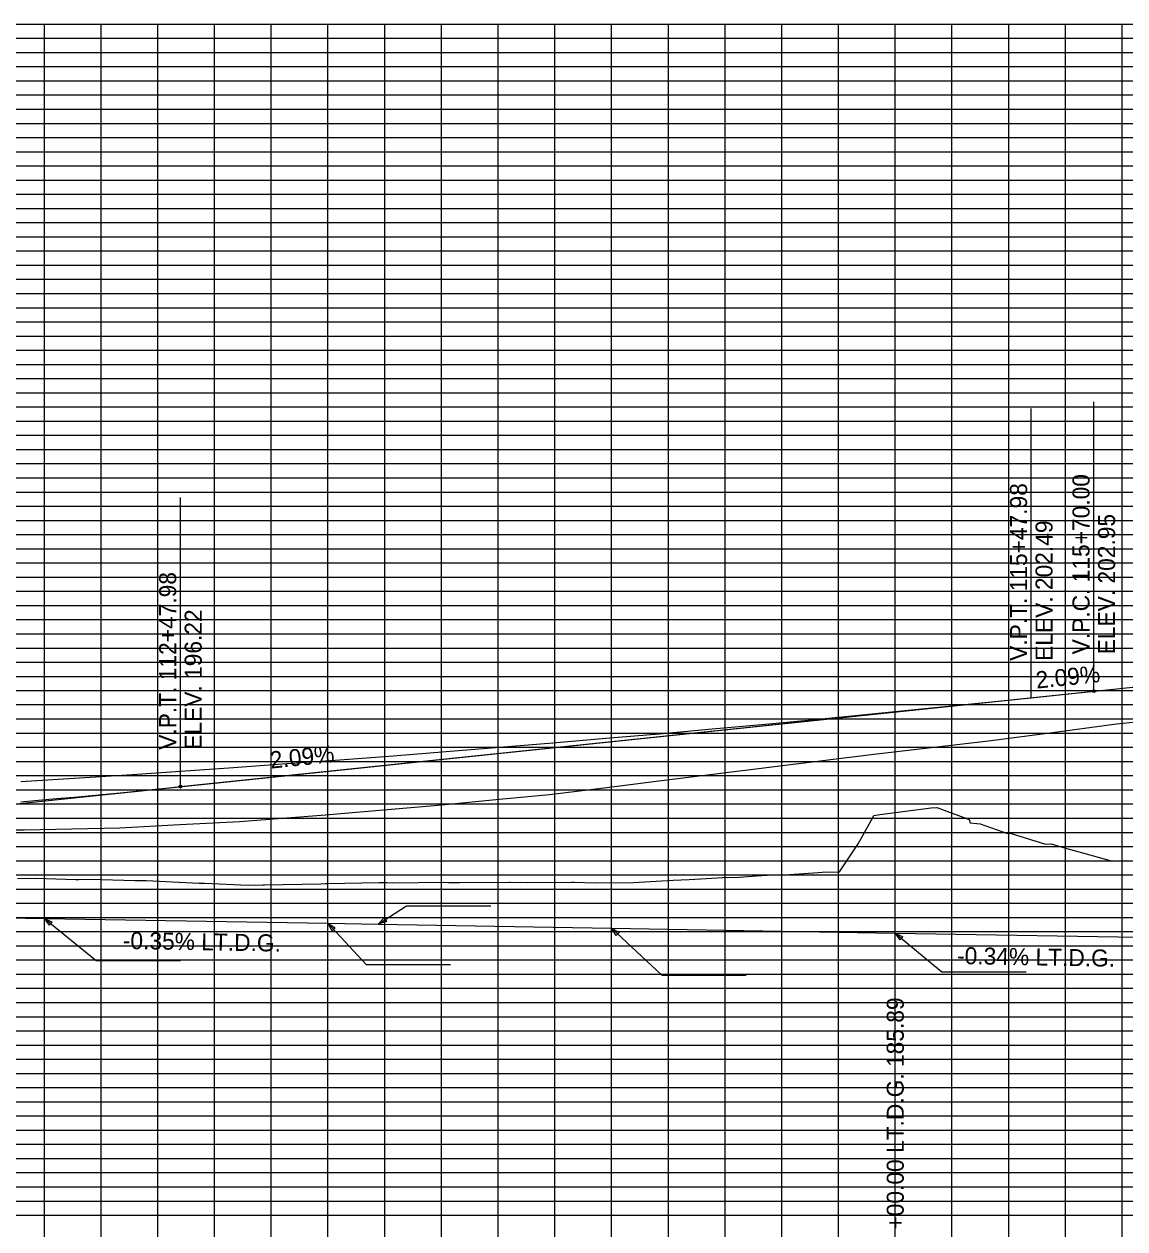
# Model space of a CAD drawing. Extents: x 1451449 to 1456010, y 297581 to 299758.
# Drawn here: x 1452672.5 to 1453060.6, y 299128.7 to 299553.5 of the extents above; entities that cross this region are included whole.
import ezdxf

# ---------------------------------------------------------------- set-up
doc = ezdxf.new("R2010")
doc.units = 0
for name, color, linetype in [('Existing Profile Grade', 7, 'Continuous'), ('Grid_Major', 7, 'Continuous'), ('Grid_Minor', 7, 'Continuous'), ('PR_Exist Surface', 7, 'Continuous'), ('PR_exist_ground', 7, 'Continuous'), ('PRF_Scratch', 7, 'Continuous'), ('Profile Annotation', 7, 'Continuous'), ('Profile Annotation Line', 7, 'Continuous'), ('Special_Ditch_LT', 7, 'Continuous')]:
    doc.layers.add(name, color=color, linetype=linetype)

msp = doc.modelspace()

# ---------------------------------------------------------------- linework, layer by layer
at = {"layer": 'Existing Profile Grade'}
msp.add_lwpolyline([(1452654.57, 299269.46), (1452672.54, 299269.39), (1452689.38, 299269.76), (1452706.22, 299270.14), (1452727.4, 299271.26), (1452748.58, 299272.38), (1452763.67, 299273.56), (1452778.75, 299274.75), (1452799.29, 299276.5), (1452819.83, 299278.26), (1452819.79, 299278.26), (1452838.79, 299280.08), (1452857.79, 299281.9), (1452877.08, 299284.29), (1452896.36, 299286.69), (1452916.28, 299289.17), (1452936.19, 299291.64), (1452954.17, 299293.85), (1452972.15, 299296.06), (1452992.35, 299298.42), (1453012.55, 299300.79), (1453035.09, 299303.78), (1453057.64, 299306.77), (1453078.47, 299308.95)], dxfattribs=at)
at = {"layer": 'Grid_Major'}
for p, q in [((1451479.67, 299553.55), (1455979.67, 299553.55)), ((1451479.67, 299553.55), (1455979.67, 299553.55)), ((1452679.67, 298953.55), (1452679.67, 299553.55)), ((1452779.67, 298953.55), (1452779.67, 299553.55)), ((1452879.67, 298953.55), (1452879.67, 299553.55)), ((1452979.67, 298953.55), (1452979.67, 299553.55)), ((1451479.67, 299503.55), (1455979.67, 299503.55)), ((1451479.67, 299453.55), (1455979.67, 299453.55)), ((1451479.67, 299403.55), (1455979.67, 299403.55)), ((1451479.67, 299353.55), (1455979.67, 299353.55)), ((1451479.67, 299303.55), (1455979.67, 299303.55)), ((1451479.67, 299253.55), (1455979.67, 299253.55)), ((1451479.67, 299203.55), (1455979.67, 299203.55)), ((1451479.67, 299153.55), (1455979.67, 299153.55))]:
    msp.add_line(p, q, dxfattribs=at)
at = {"layer": 'Grid_Minor'}
for p, q in [((1452699.67, 298953.55), (1452699.67, 299553.55)), ((1452719.67, 298953.55), (1452719.67, 299553.55)), ((1452739.67, 298953.55), (1452739.67, 299553.55)), ((1452759.67, 298953.55), (1452759.67, 299553.55)), ((1452799.67, 298953.55), (1452799.67, 299553.55)), ((1452819.67, 298953.55), (1452819.67, 299553.55)), ((1452839.67, 298953.55), (1452839.67, 299553.55)), ((1452859.67, 298953.55), (1452859.67, 299553.55)), ((1452899.67, 298953.55), (1452899.67, 299553.55)), ((1452919.67, 298953.55), (1452919.67, 299553.55)), ((1452939.67, 298953.55), (1452939.67, 299553.55)), ((1452959.67, 298953.55), (1452959.67, 299553.55)), ((1452999.67, 298953.55), (1452999.67, 299553.55)), ((1453019.67, 298953.55), (1453019.67, 299553.55)), ((1453039.67, 298953.55), (1453039.67, 299553.55)), ((1453059.67, 298953.55), (1453059.67, 299553.55)), ((1451479.67, 299548.55), (1455979.67, 299548.55)), ((1451479.67, 299543.55), (1455979.67, 299543.55)), ((1451479.67, 299538.55), (1455979.67, 299538.55)), ((1451479.67, 299533.55), (1455979.67, 299533.55)), ((1451479.67, 299528.55), (1455979.67, 299528.55)), ((1451479.67, 299523.55), (1455979.67, 299523.55)), ((1451479.67, 299518.55), (1455979.67, 299518.55)), ((1451479.67, 299513.55), (1455979.67, 299513.55)), ((1451479.67, 299508.55), (1455979.67, 299508.55)), ((1451479.67, 299498.55), (1455979.67, 299498.55)), ((1451479.67, 299493.55), (1455979.67, 299493.55)), ((1451479.67, 299488.55), (1455979.67, 299488.55)), ((1451479.67, 299483.55), (1455979.67, 299483.55)), ((1451479.67, 299478.55), (1455979.67, 299478.55)), ((1451479.67, 299473.55), (1455979.67, 299473.55)), ((1451479.67, 299468.55), (1455979.67, 299468.55)), ((1451479.67, 299463.55), (1455979.67, 299463.55)), ((1451479.67, 299458.55), (1455979.67, 299458.55)), ((1451479.67, 299448.55), (1455979.67, 299448.55)), ((1451479.67, 299443.55), (1455979.67, 299443.55)), ((1451479.67, 299438.55), (1455979.67, 299438.55)), ((1451479.67, 299433.55), (1455979.67, 299433.55)), ((1451479.67, 299428.55), (1455979.67, 299428.55)), ((1451479.67, 299423.55), (1455979.67, 299423.55)), ((1451479.67, 299418.55), (1455979.67, 299418.55)), ((1451479.67, 299413.55), (1455979.67, 299413.55)), ((1451479.67, 299408.55), (1455979.67, 299408.55)), ((1451479.67, 299398.55), (1455979.67, 299398.55)), ((1451479.67, 299393.55), (1455979.67, 299393.55)), ((1451479.67, 299388.55), (1455979.67, 299388.55)), ((1451479.67, 299383.55), (1455979.67, 299383.55)), ((1451479.67, 299378.55), (1455979.67, 299378.55)), ((1451479.67, 299373.55), (1455979.67, 299373.55)), ((1451479.67, 299368.55), (1455979.67, 299368.55)), ((1451479.67, 299363.55), (1455979.67, 299363.55)), ((1451479.67, 299358.55), (1455979.67, 299358.55)), ((1451479.67, 299348.55), (1455979.67, 299348.55)), ((1451479.67, 299343.55), (1455979.67, 299343.55)), ((1451479.67, 299338.55), (1455979.67, 299338.55)), ((1451479.67, 299333.55), (1455979.67, 299333.55)), ((1451479.67, 299328.55), (1455979.67, 299328.55)), ((1451479.67, 299323.55), (1455979.67, 299323.55)), ((1451479.67, 299318.55), (1455979.67, 299318.55)), ((1451482.2, 299313.64), (1455982.2, 299313.64)), ((1451479.67, 299308.55), (1455979.67, 299308.55)), ((1451479.67, 299298.55), (1455979.67, 299298.55)), ((1451479.67, 299293.55), (1455979.67, 299293.55)), ((1451479.67, 299288.55), (1455979.67, 299288.55)), ((1451479.67, 299283.55), (1455979.67, 299283.55)), ((1451479.67, 299278.55), (1455979.67, 299278.55)), ((1451479.67, 299273.55), (1455979.67, 299273.55)), ((1451479.67, 299268.55), (1455979.67, 299268.55)), ((1451479.67, 299263.55), (1455979.67, 299263.55)), ((1451479.67, 299258.55), (1455979.67, 299258.55)), ((1451479.67, 299248.55), (1455979.67, 299248.55)), ((1451479.67, 299243.55), (1455979.67, 299243.55)), ((1451479.67, 299238.55), (1455979.67, 299238.55)), ((1451479.67, 299233.55), (1455979.67, 299233.55)), ((1451479.67, 299228.55), (1455979.67, 299228.55)), ((1451479.67, 299223.55), (1455979.67, 299223.55)), ((1451479.67, 299218.55), (1455979.67, 299218.55)), ((1451479.67, 299213.55), (1455979.67, 299213.55)), ((1451479.67, 299208.55), (1455979.67, 299208.55)), ((1451479.67, 299198.55), (1455979.67, 299198.55)), ((1451479.67, 299193.55), (1455979.67, 299193.55)), ((1451479.67, 299188.55), (1455979.67, 299188.55)), ((1451479.67, 299183.55), (1455979.67, 299183.55)), ((1451479.67, 299178.55), (1455979.67, 299178.55)), ((1451479.67, 299173.55), (1455979.67, 299173.55)), ((1451479.67, 299168.55), (1455979.67, 299168.55)), ((1451479.67, 299163.55), (1455979.67, 299163.55)), ((1451479.67, 299158.55), (1455979.67, 299158.55)), ((1451479.67, 299148.55), (1455979.67, 299148.55)), ((1451479.67, 299143.55), (1455979.67, 299143.55)), ((1451479.67, 299138.55), (1455979.67, 299138.55)), ((1451479.67, 299133.55), (1455979.67, 299133.55))]:
    msp.add_line(p, q, dxfattribs=at)
at = {"layer": 'PR_Exist Surface'}
msp.add_lwpolyline([(1452670.16, 299252.28), (1452676.62, 299252.38), (1452690.76, 299251.94), (1452691.87, 299251.96), (1452695.98, 299252.01), (1452711.61, 299251.53), (1452713.59, 299251.54), (1452715.57, 299251.57), (1452734.23, 299250.68), (1452735.31, 299250.64), (1452736.18, 299250.6), (1452751.52, 299249.9), (1452756.73, 299249.99), (1452757.03, 299250), (1452757.27, 299250.01), (1452777.2, 299250.42), (1452778.75, 299250.47), (1452779.54, 299250.49), (1452797.66, 299250.89), (1452800.47, 299250.83), (1452802.51, 299250.79), (1452820.56, 299250.96), (1452822.18, 299250.92), (1452826.11, 299250.82), (1452843.48, 299251), (1452843.9, 299250.98), (1452849.86, 299250.82), (1452865.62, 299250.99), (1452866.41, 299251), (1452873.85, 299250.75), (1452887.34, 299250.92), (1452889.35, 299250.95), (1452901.4, 299251.73), (1452907.02, 299251.87), (1452909.06, 299252), (1452918.86, 299252.64), (1452924.69, 299252.79), (1452930.78, 299253.19), (1452936.36, 299253.56), (1452942.37, 299253.71), (1452952.49, 299254.39), (1452953.9, 299254.49), (1452960.05, 299254.64), (1452966.63, 299264.54), (1452970.51, 299271.47), (1452972.09, 299274.54), (1452974.21, 299274.82), (1452992.38, 299277.24), (1452994.39, 299277.35), (1452995.93, 299276.77), (1453005.69, 299273.09), (1453006.14, 299271.95), (1453009.65, 299271.53), (1453017.65, 299268.74), (1453019.26, 299268.18), (1453020.21, 299268.23), (1453032.61, 299264.37), (1453034.62, 299264.45), (1453039.37, 299263.11), (1453046.21, 299261.19), (1453056.25, 299258.39), (1453060, 299258.49), (1453061.09, 299258.58)], dxfattribs=at)
at = {"layer": 'PR_exist_ground'}
for p, q in [((1453027.64, 299316.01), (1453049.67, 299318.31)), ((1453027.64, 299316.01), (1453049.67, 299318.31)), ((1453027.64, 299316.01), (1453049.67, 299318.31)), ((1453027.64, 299316.01), (1453049.67, 299318.31)), ((1453027.64, 299316.01), (1453049.67, 299318.31)), ((1452810.4, 299242.6), (1452837.14, 299242.6)), ((1452700.88, 299223.34), (1452727.63, 299223.34)), ((1452796.1, 299221.97), (1452822.85, 299221.97)), ((1452900.4, 299218.21), (1452927.15, 299218.21)), ((1452999.07, 299219.31), (1453025.82, 299219.31))]:
    msp.add_line(p, q, dxfattribs=at)
for points in [[(1453049.67, 299318.31), (1453063.42, 299319.72)], [(1453049.67, 299318.31), (1453063.42, 299319.72)], [(1453049.67, 299318.31), (1453063.42, 299319.72)], [(1453049.67, 299318.31), (1453063.42, 299319.72)], [(1453049.67, 299318.31), (1453063.42, 299319.72)], [(1452671.39, 299286.5), (1452690.14, 299287.67), (1452708.89, 299288.88), (1452727.64, 299290.13), (1452746.39, 299291.43), (1452765.14, 299292.77), (1452783.89, 299294.15), (1452802.64, 299295.58), (1452821.39, 299297.04), (1452840.14, 299298.55), (1452858.89, 299300.11), (1452877.64, 299301.7), (1452896.39, 299303.34), (1452915.14, 299305.02), (1452933.89, 299306.75), (1452952.64, 299308.51), (1452971.39, 299310.32), (1452990.14, 299312.18), (1453008.89, 299314.07), (1453027.64, 299316.01)], [(1452671.39, 299286.5), (1452690.14, 299287.67), (1452708.89, 299288.88), (1452727.64, 299290.13), (1452746.39, 299291.43), (1452765.14, 299292.77), (1452783.89, 299294.15), (1452802.64, 299295.58), (1452821.39, 299297.04), (1452840.14, 299298.55), (1452858.89, 299300.11), (1452877.64, 299301.7), (1452896.39, 299303.34), (1452915.14, 299305.02), (1452933.89, 299306.75), (1452952.64, 299308.51), (1452971.39, 299310.32), (1452990.14, 299312.18), (1453008.89, 299314.07), (1453027.64, 299316.01)], [(1452671.39, 299286.5), (1452690.14, 299287.67), (1452708.89, 299288.88), (1452727.64, 299290.13), (1452746.39, 299291.43), (1452765.14, 299292.77), (1452783.89, 299294.15), (1452802.64, 299295.58), (1452821.39, 299297.04), (1452840.14, 299298.55), (1452858.89, 299300.11), (1452877.64, 299301.7), (1452896.39, 299303.34), (1452915.14, 299305.02), (1452933.89, 299306.75), (1452952.64, 299308.51), (1452971.39, 299310.32), (1452990.14, 299312.18), (1453008.89, 299314.07), (1453027.64, 299316.01)], [(1452671.39, 299286.5), (1452690.14, 299287.67), (1452708.89, 299288.88), (1452727.64, 299290.13), (1452746.39, 299291.43), (1452765.14, 299292.77), (1452783.89, 299294.15), (1452802.64, 299295.58), (1452821.39, 299297.04), (1452840.14, 299298.55), (1452858.89, 299300.11), (1452877.64, 299301.7), (1452896.39, 299303.34), (1452915.14, 299305.02), (1452933.89, 299306.75), (1452952.64, 299308.51), (1452971.39, 299310.32), (1452990.14, 299312.18), (1453008.89, 299314.07), (1453027.64, 299316.01)], [(1452671.39, 299286.5), (1452690.14, 299287.67), (1452708.89, 299288.88), (1452727.64, 299290.13), (1452746.39, 299291.43), (1452765.14, 299292.77), (1452783.89, 299294.15), (1452802.64, 299295.58), (1452821.39, 299297.04), (1452840.14, 299298.55), (1452858.89, 299300.11), (1452877.64, 299301.7), (1452896.39, 299303.34), (1452915.14, 299305.02), (1452933.89, 299306.75), (1452952.64, 299308.51), (1452971.39, 299310.32), (1452990.14, 299312.18), (1453008.89, 299314.07), (1453027.64, 299316.01)], [(1452797.41, 299236.16), (1452807.4, 299242.6), (1452810.4, 299242.6)], [(1452679.67, 299238.2), (1452697.88, 299223.34), (1452700.88, 299223.34)], [(1452779.67, 299236.47), (1452793.1, 299221.97), (1452796.1, 299221.97)], [(1452879.67, 299234.75), (1452897.4, 299218.21), (1452900.4, 299218.21)], [(1452979.67, 299233.02), (1452996.07, 299219.31), (1452999.07, 299219.31)]]:
    msp.add_lwpolyline(points, dxfattribs=at)
for points in [[(1452797.41, 299236.16), (1452799.47, 299238.35), (1452800.25, 299237.13)], [(1452679.67, 299238.2), (1452682.38, 299236.92), (1452681.46, 299235.79)], [(1452779.67, 299236.47), (1452782.18, 299234.83), (1452781.11, 299233.84)], [(1452879.67, 299234.75), (1452882.29, 299233.29), (1452881.3, 299232.23)], [(1452979.67, 299233.02), (1452982.37, 299231.71), (1452981.43, 299230.6)]]:
    msp.add_lwpolyline(points, close=True, dxfattribs=at)
at = {"layer": 'PRF_Scratch'}
for p, q in [((1453049.67, 299318.31), (1453049.67, 299420.31)), ((1452727.64, 299284.66), (1452727.64, 299386.66)), ((1452577.64, 299268.98), (1453379.67, 299352.79)), ((1452577.64, 299268.98), (1453379.67, 299352.79)), ((1452577.64, 299268.98), (1453379.67, 299352.79)), ((1452577.64, 299268.98), (1453379.67, 299352.79)), ((1452577.64, 299268.98), (1453379.67, 299352.79)), ((1452577.64, 299268.98), (1453379.67, 299352.79)), ((1452727.64, 299284.66), (1453379.67, 299352.79)), ((1452727.64, 299284.66), (1453049.67, 299318.31)), ((1452727.64, 299284.66), (1453049.67, 299318.31)), ((1452727.64, 299284.66), (1453049.67, 299318.31)), ((1452727.64, 299284.66), (1453049.67, 299318.31)), ((1452727.64, 299284.66), (1453049.67, 299318.31))]:
    msp.add_line(p, q, dxfattribs=at)
for points in [[(1453049.67, 299318.31), (1453063.42, 299319.72)], [(1453049.67, 299318.31), (1453063.42, 299319.72)], [(1453049.67, 299318.31), (1453063.42, 299319.72)], [(1452671.39, 299279.36), (1452677.64, 299279.89), (1452683.89, 299280.44), (1452690.14, 299281), (1452696.39, 299281.57), (1452702.64, 299282.16), (1452708.89, 299282.76), (1452715.14, 299283.38), (1452721.39, 299284.01), (1452727.64, 299284.66)], [(1452671.39, 299279.36), (1452677.64, 299279.89), (1452683.89, 299280.44), (1452690.14, 299281), (1452696.39, 299281.57), (1452702.64, 299282.16), (1452708.89, 299282.76), (1452715.14, 299283.38), (1452721.39, 299284.01), (1452727.64, 299284.66)], [(1452671.39, 299279.36), (1452677.64, 299279.89), (1452683.89, 299280.44), (1452690.14, 299281), (1452696.39, 299281.57), (1452702.64, 299282.16), (1452708.89, 299282.76), (1452715.14, 299283.38), (1452721.39, 299284.01), (1452727.64, 299284.66)], [(1452671.39, 299279.36), (1452677.64, 299279.89), (1452683.89, 299280.44), (1452690.14, 299281), (1452696.39, 299281.57), (1452702.64, 299282.16), (1452708.89, 299282.76), (1452715.14, 299283.38), (1452721.39, 299284.01), (1452727.64, 299284.66)], [(1452671.39, 299279.36), (1452677.64, 299279.89), (1452683.89, 299280.44), (1452690.14, 299281), (1452696.39, 299281.57), (1452702.64, 299282.16), (1452708.89, 299282.76), (1452715.14, 299283.38), (1452721.39, 299284.01), (1452727.64, 299284.66)], [(1452671.39, 299279.36), (1452677.64, 299279.89), (1452683.89, 299280.44), (1452690.14, 299281), (1452696.39, 299281.57), (1452702.64, 299282.16), (1452708.89, 299282.76), (1452715.14, 299283.38), (1452721.39, 299284.01), (1452727.64, 299284.66)]]:
    msp.add_lwpolyline(points, dxfattribs=at)
for centre in [(1453049.67, 299318.31), (1453049.67, 299318.31), (1453049.67, 299318.31), (1453049.67, 299318.31), (1452727.64, 299284.66), (1452727.64, 299284.66), (1452727.64, 299284.66), (1452727.64, 299284.66), (1452727.64, 299284.66)]:
    msp.add_circle(centre, 0.5, dxfattribs=at)
at = {"layer": 'Profile Annotation Line'}
for p, q in [((1453027.64, 299316.01), (1453027.64, 299418.01)), ((1453049.67, 299318.31), (1453049.67, 299420.31)), ((1452577.64, 299268.98), (1452802.64, 299292.5))]:
    msp.add_line(p, q, dxfattribs=at)
at = {"layer": 'Special_Ditch_LT'}
msp.add_lwpolyline([(1452379.67, 299242.2), (1452479.67, 299241.65), (1452579.67, 299239.92), (1452679.67, 299238.2), (1452779.67, 299236.47), (1452797.41, 299236.16), (1452879.67, 299234.75), (1452979.67, 299233.02), (1453079.67, 299231.3), (1453179.67, 299228.1), (1453245.59, 299226.55)], dxfattribs=at)

# ---------------------------------------------------------------- texts
at = {"layer": 'PRF_Scratch'}
for s, rotation, p in [('V.P.C. 115+70.00', 90, (1453048.17, 299331.31)), ('ELEV. 202.95', 90, (1453057.17, 299331.31)), ('V.P.T. 112+47.98', 90, (1452726.14, 299297.66)), ('ELEV. 196.22', 90, (1452735.14, 299297.66)), ('2.09%', 5.9657, (1452759.53, 299291.01))]:
    msp.add_text(s, height=6, rotation=rotation, dxfattribs=at).set_placement(p)
at = {"layer": 'Profile Annotation'}
for s, rotation, p in [('V.P.T. 115+47.98', 90, (1453026.14, 299329.01)), ('V.P.C. 115+70.00', 90, (1453048.17, 299331.31)), ('ELEV. 202.95', 90, (1453057.17, 299331.31)), ('ELEV. 202.49', 90, (1453035.14, 299329.01)), ('2.09%', 5.9657, (1453029.53, 299319.22)), ('-0.35% LT.D.G.', 359.0117, (1452707.29, 299227.46)), ('-0.34% LT.D.G.', 359.0117, (1453001.43, 299222.11)), ('+00.00 LT.D.G. 185.89', 90, (1452982.67, 299128.5))]:
    msp.add_text(s, height=6, rotation=rotation, dxfattribs=at).set_placement(p)

doc.saveas('drawing.dxf')
